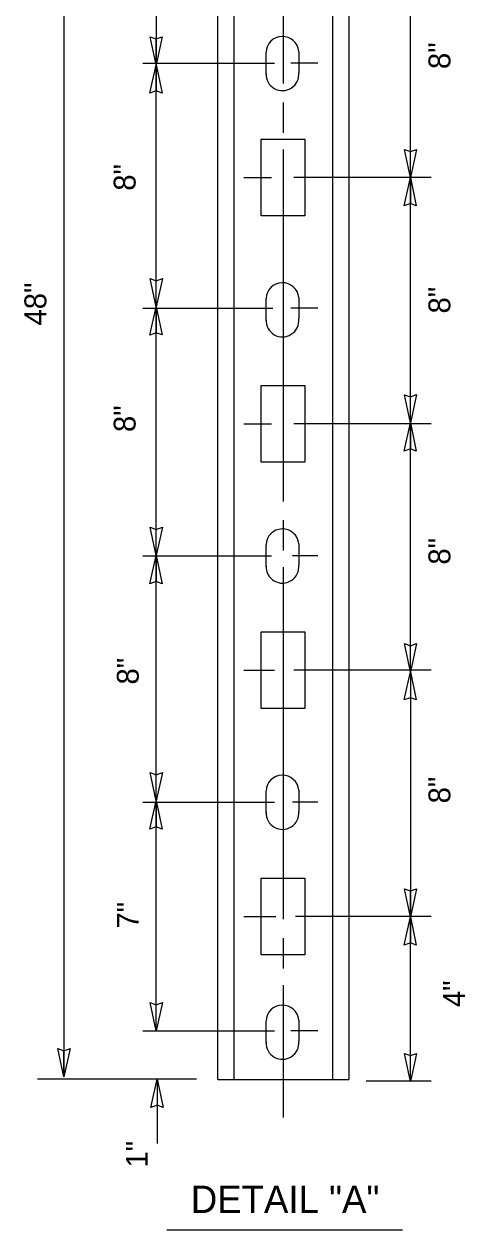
# Model space of a CAD drawing. Extents: x 19188 to 19495, y 20866 to 21061.
# Drawn here: x 19189.34 to 19205.22, y 20889.47 to 20932.89 of the extents above; entities that cross this region are included whole.
import ezdxf

# ---------------------------------------------------------------- set-up
doc = ezdxf.new("R2010")
doc.units = 0
doc.layers.add('G-ANNO-NOTE', color=7, linetype='Continuous')

msp = doc.modelspace()

# ---------------------------------------------------------------- linework, layer by layer
at = {"layer": 'G-ANNO-NOTE'}
for p, q in [((19190.773, 20950.381), (19190.773, 20894.983)), ((19196.314, 20894.88), (19196.314, 20950.408)), ((19196.905, 20894.88), (19196.905, 20950.408)), ((19200.452, 20950.408), (19200.452, 20894.88)), ((19201.043, 20950.408), (19201.043, 20894.88)), ((19194.096, 20940.38), (19194.097, 20931.42)), ((19203.255, 20927.363), (19203.255, 20936.195)), ((19194.097, 20931.42), (19194.097, 20932.356)), ((19198.053, 20931.874), (19198.053, 20931.086)), ((19199.236, 20931.91), (19199.236, 20931.141)), ((19193.617, 20931.48), (19198.357, 20931.48)), ((19194.098, 20922.714), (19194.097, 20931.42)), ((19194.097, 20931.42), (19194.097, 20930.484)), ((19199.924, 20931.48), (19198.952, 20931.48)), ((19197.876, 20928.742), (19199.452, 20928.742)), ((19197.876, 20925.983), (19197.876, 20928.742)), ((19199.452, 20928.742), (19199.452, 20925.983)), ((19203.255, 20927.363), (19203.255, 20928.299)), ((19197.261, 20927.363), (19198.248, 20927.363)), ((19204.003, 20927.363), (19199.06, 20927.363)), ((19203.255, 20918.53), (19203.255, 20927.363)), ((19203.255, 20927.363), (19203.255, 20926.426)), ((19199.452, 20925.983), (19197.876, 20925.983)), ((19194.098, 20922.714), (19194.097, 20923.65)), ((19194.098, 20913.754), (19194.098, 20922.714)), ((19194.098, 20922.714), (19194.098, 20921.777)), ((19198.053, 20923.005), (19198.053, 20922.217)), ((19199.236, 20923.042), (19199.236, 20922.272)), ((19193.618, 20922.657), (19198.302, 20922.657)), ((19199.925, 20922.657), (19198.952, 20922.657)), ((19197.876, 20919.873), (19199.452, 20919.873)), ((19197.876, 20917.114), (19197.876, 20919.873)), ((19199.452, 20919.873), (19199.452, 20917.114)), ((19203.255, 20918.53), (19203.255, 20919.466)), ((19197.262, 20918.494), (19198.248, 20918.494)), ((19204.003, 20918.494), (19199.06, 20918.494)), ((19203.255, 20909.57), (19203.255, 20918.53)), ((19203.255, 20918.53), (19203.255, 20917.593)), ((19199.452, 20917.114), (19197.876, 20917.114)), ((19194.098, 20913.754), (19194.098, 20914.69)), ((19198.053, 20914.137), (19198.053, 20913.348)), ((19199.236, 20914.173), (19199.236, 20913.404)), ((19193.618, 20913.742), (19198.248, 20913.743)), ((19194.099, 20904.921), (19194.098, 20913.754)), ((19194.098, 20913.754), (19194.098, 20912.818)), ((19199.925, 20913.743), (19199.006, 20913.743)), ((19197.876, 20911.005), (19199.452, 20911.005)), ((19197.876, 20908.245), (19197.876, 20911.005)), ((19199.452, 20911.005), (19199.452, 20908.245)), ((19203.255, 20909.57), (19203.255, 20910.506)), ((19197.262, 20909.625), (19198.357, 20909.625)), ((19204.003, 20909.625), (19199.06, 20909.625)), ((19203.255, 20909.57), (19203.255, 20900.737)), ((19203.255, 20909.57), (19203.255, 20908.633)), ((19199.452, 20908.245), (19197.876, 20908.245)), ((19194.099, 20904.921), (19194.099, 20905.857)), ((19194.1, 20896.642), (19194.099, 20904.921)), ((19194.099, 20904.921), (19194.099, 20903.985)), ((19198.053, 20905.268), (19198.053, 20904.479)), ((19199.236, 20905.304), (19199.236, 20904.535)), ((19193.619, 20904.874), (19198.357, 20904.874)), ((19199.926, 20904.874), (19199.006, 20904.874)), ((19197.876, 20902.136), (19199.452, 20902.136)), ((19197.876, 20899.376), (19197.876, 20902.136)), ((19199.452, 20902.136), (19199.452, 20899.376)), ((19203.255, 20900.737), (19203.255, 20901.673)), ((19197.262, 20900.756), (19198.411, 20900.756)), ((19204.003, 20900.756), (19199.114, 20900.756)), ((19203.255, 20894.807), (19203.255, 20900.737)), ((19203.255, 20900.737), (19203.255, 20899.801)), ((19199.452, 20899.376), (19197.876, 20899.376)), ((19194.1, 20896.642), (19194.1, 20897.578)), ((19198.053, 20896.99), (19198.053, 20896.202)), ((19199.236, 20897.026), (19199.236, 20896.257)), ((19193.62, 20896.642), (19198.357, 20896.642)), ((19199.927, 20896.642), (19198.952, 20896.642)), ((19190.773, 20894.983), (19190.773, 20895.919)), ((19203.255, 20894.807), (19203.255, 20895.743)), ((19195.549, 20894.895), (19189.822, 20894.895)), ((19194.132, 20894.895), (19194.132, 20892.574)), ((19194.132, 20894.895), (19194.132, 20893.959)), ((19196.314, 20894.88), (19201.043, 20894.88)), ((19201.66, 20894.841), (19204.003, 20894.841)), ((19194.478, 20889.468), (19202.969, 20889.468))]:
    msp.add_line(p, q, dxfattribs=at)
for points in [[(19198.679, 20938.656), (19198.679, 20930.749)], [(19194.097, 20932.356), (19194.32, 20932.438), (19194.097, 20931.42), (19193.883, 20932.436), (19194.097, 20932.356)], [(19194.097, 20930.483), (19193.873, 20930.402), (19194.097, 20931.42), (19194.311, 20930.404), (19194.097, 20930.483)], [(19198.679, 20930.066), (19198.679, 20928.975)], [(19198.679, 20928.374), (19198.679, 20923.611)], [(19203.255, 20928.299), (19203.479, 20928.381), (19203.255, 20927.363), (19203.041, 20928.379), (19203.255, 20928.299)], [(19203.255, 20926.426), (19203.031, 20926.344), (19203.255, 20927.363), (19203.469, 20926.347), (19203.255, 20926.426)], [(19194.097, 20923.65), (19194.321, 20923.732), (19194.098, 20922.714), (19193.884, 20923.73), (19194.097, 20923.65)], [(19198.679, 20923.611), (19198.679, 20915.703)], [(19194.098, 20921.777), (19193.874, 20921.695), (19194.098, 20922.714), (19194.311, 20921.697), (19194.098, 20921.777)], [(19203.255, 20919.466), (19203.479, 20919.548), (19203.255, 20918.53), (19203.041, 20919.546), (19203.255, 20919.466)], [(19203.255, 20917.593), (19203.031, 20917.511), (19203.255, 20918.53), (19203.469, 20917.514), (19203.255, 20917.593)], [(19198.679, 20915.021), (19198.679, 20913.929)], [(19194.098, 20914.69), (19194.322, 20914.772), (19194.098, 20913.754), (19193.884, 20914.77), (19194.098, 20914.69)], [(19194.099, 20912.817), (19193.875, 20912.735), (19194.098, 20913.754), (19194.312, 20912.738), (19194.099, 20912.817)], [(19198.679, 20913.329), (19198.679, 20908.566)], [(19203.255, 20910.506), (19203.479, 20910.588), (19203.255, 20909.57), (19203.041, 20910.586), (19203.255, 20910.506)], [(19203.255, 20908.633), (19203.031, 20908.551), (19203.255, 20909.57), (19203.469, 20908.554), (19203.255, 20908.633)], [(19198.679, 20908.566), (19198.679, 20900.658)], [(19194.099, 20905.857), (19194.323, 20905.94), (19194.099, 20904.921), (19193.885, 20905.937), (19194.099, 20905.857)], [(19194.099, 20903.985), (19193.875, 20903.902), (19194.099, 20904.921), (19194.313, 20903.905), (19194.099, 20903.985)], [(19203.255, 20901.673), (19203.479, 20901.755), (19203.255, 20900.737), (19203.041, 20901.753), (19203.255, 20901.673)], [(19203.255, 20899.8), (19203.031, 20899.718), (19203.255, 20900.737), (19203.469, 20899.721), (19203.255, 20899.8)], [(19198.679, 20899.976), (19198.679, 20898.884)], [(19198.679, 20898.284), (19198.679, 20893.52)], [(19194.1, 20897.578), (19194.323, 20897.66), (19194.1, 20896.642), (19193.886, 20897.658), (19194.1, 20897.578)], [(19190.773, 20895.919), (19190.996, 20896.001), (19190.773, 20894.983), (19190.559, 20896), (19190.773, 20895.919)], [(19203.255, 20895.743), (19203.479, 20895.825), (19203.255, 20894.807), (19203.041, 20895.823), (19203.255, 20895.743)], [(19194.132, 20893.958), (19193.908, 20893.876), (19194.132, 20894.895), (19194.346, 20893.879), (19194.132, 20893.958)]]:
    msp.add_lwpolyline(points, dxfattribs=at)
for centre, start, end in [((19198.647, 20931.856), 5.267, 177.6123), ((19198.647, 20931.087), 177.6721, 5.267), ((19198.647, 20922.987), 5.267, 177.6123), ((19198.647, 20922.218), 177.6721, 5.267), ((19198.647, 20914.119), 5.267, 177.6123), ((19198.647, 20913.35), 177.6721, 5.267), ((19198.647, 20905.25), 5.267, 177.6123), ((19198.647, 20904.481), 177.6721, 5.267), ((19198.647, 20896.972), 5.267, 177.6123), ((19198.647, 20896.203), 177.6721, 5.267)]:
    msp.add_arc(centre, 0.591, start, end, dxfattribs=at)

# ---------------------------------------------------------------- texts
for s, p in [('8"', (19204.696, 20931.272)), ('8"', (19193.357, 20926.89)), ('48"', (19190.141, 20922.036)), ('8"', (19204.696, 20922.47)), ('8"', (19193.357, 20918.2)), ('8"', (19204.696, 20913.426)), ('8"', (19193.47, 20909.109)), ('8"', (19204.696, 20904.827)), ('7"', (19193.471, 20900.318)), ('4"', (19205.22, 20897.489)), ('1"', (19193.798, 20891.712))]:
    msp.add_text(s, height=0.7883, rotation=90, dxfattribs=at).set_placement(p)
msp.add_text('DETAIL "A"', height=0.9854, dxfattribs=at).set_placement((19195.347, 20890.077))

doc.saveas('drawing.dxf')
